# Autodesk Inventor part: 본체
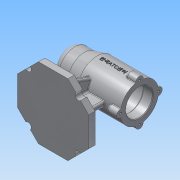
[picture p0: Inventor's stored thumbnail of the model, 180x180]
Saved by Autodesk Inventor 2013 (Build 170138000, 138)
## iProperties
Created: 2019-12
Part Number: 본체
Material: 알루미늄 6061
Document SubType Name: Modeling
Designer: Administrator
Density: 2.71 g/cm^3
Mass: 728.059 g
Surface Area: 716.508 cm^2
Volume: 268.657 cm^3
Author: Administrator
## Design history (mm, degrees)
sketch "스케치1"
  geometry: L1 (-56, 0)-(56, 0); L2 (-56, 0)-(-56, 25); L3 (-56, 25)-(-31, 25); L4 (-31, 25)-(-11, 30); L5 (-11, 30)-(56, 30); L6 (56, 30)-(56, 0); 2 further points
  constraints: 12 end point, 2 parallel, 2 perpendicular, 1 coincident, 1 horizontal, 1 midpoint
  dimensions: "d0" = 112 distance of L1.start L1.end; "d2" = 25 distance from line of L3.end L2; "d3" = 45 distance from line of L2 L4.end; "d4" = 50 diameter of L3 L1; "d5" = 60 diameter of L5 L1
revolve "회전1" sketch "스케치1" stored, may be unused: angle "d6" = 90 deg
node "작업 평면1"
sketch "스케치2" dims "d8" = 112
  geometry: L1 (23.196, 56)-(56, 23.196); L2 (56, 23.196)-(56, -23.196); L3 (56, -23.196)-(23.196, -56); L4 (23.196, -56)-(-23.196, -56); L5 (-23.196, -56)-(-56, -23.196); L6 (-56, -23.196)-(-56, 23.196); L7 (-56, 23.196)-(-23.196, 56); L8 (-23.196, 56)-(23.196, 56); 4 further points
  constraints: 16 end point, 2 coincident, 1 midpoint, 1 vertical alignment, 19 other
extrude "돌출1" join sketch "스케치2" distance "d9" = 10; taper "d10" = 0 deg
sketch "스케치4"
  geometry: L1 (-80, 56)-(-70, 56) reference; L2 (-70, 56)-(-70, -56) reference; L3 (-70, -56)-(-80, -56) reference; L4 (-80, -56)-(-80, 56) reference; L5 (-70, 0)-(0, 0); L6 (0, 0)-(0, -10.522); L7 (0, -10.522)-(-70, -36); L8 (-70, 0)-(-70, -36); C1 r 30 at (0, 0) reference; 1 further point
  constraints: 8 end point, 2 perpendicular, 1 collinear, 1 midpoint, 1 point on line
  dimensions: "d11" = 110 deg angle of L2 L7; "d12" = 20 distance from line of L3 L7.end
extrude "돌출2" join sketch "스케치4" stored distance "d13" = 8; taper "d14" = 0 deg
sketch "스케치5"
  geometry: L1 (-56, -25)-(-56, 25) reference; L2 (-56, 25)-(-31, 25) reference; L3 (-31, 25)-(-11, 30) reference; L4 (-11, 30)-(56, 30) reference; L5 (56, 30)-(56, -30) reference; L6 (56, -30)-(4, -30) reference; L7 (4, -30)-(4, -70) reference; L8 (4, -70)-(56, -70) reference; L9 (56, -70)-(56, -80) reference; L10 (56, -80)-(-56, -80) reference; L11 (-56, -80)-(-56, -70) reference; L12 (-56, -70)-(-4, -70) reference; L13 (-4, -70)-(-4, -30) reference; L14 (-4, -30)-(-11, -30) reference; L15 (-11, -30)-(-31, -25) reference; L16 (-31, -25)-(-56, -25) reference; L17 (31, -70)-(31, 0); L18 (31, 0)-(-5.358, 0); L19 (-5.358, 0)-(-38, -70); L20 (31, -70)-(-38, -70); 1 further point
  constraints: 8 end point, 3 point on line, 2 perpendicular, 1 parallel
  dimensions: "d15" = 115 deg angle of L12 L19; "d16" = 18 distance from line of L11 L19.end; "d17" = 25 distance of L8.end L17.start
extrude "돌출3" join sketch "스케치5" stored distance "d18" = 8; taper "d19" = 0 deg
sketch "스케치6"
  geometry: L1 (-56, -25)-(-56, 25) reference; L2 (-56, 25)-(-31, 25) reference; L3 (-31, 25)-(-11, 30) reference; L4 (-11, 30)-(56, 30) reference; L5 (56, 30)-(56, -30) reference; L6 (56, -30)-(31, -30) reference; L7 (31, -30)-(31, -70) reference; L8 (31, -70)-(56, -70) reference; L9 (56, -70)-(56, -80) reference; L10 (56, -80)-(-56, -80) reference; L11 (-56, -80)-(-56, -70) reference; L12 (-56, -70)-(-38, -70) reference; L13 (-38, -70)-(-18.476, -28.131) reference; L14 (-18.476, -28.131)-(-31, -25) reference; L15 (-31, -25)-(-56, -25) reference; L16 (-56, 0)-(56, 0); L17 (-50, 0)-(-50, 10.5); L18 (-50, 10.5)-(-47, 10.5); L19 (-47, 10.5)-(-47, 16); L20 (-47, 16)-(-43, 16); L21 (-43, 16)-(-43, 17.5); L22 (-43, 17.5)-(-25, 17.5); L23 (-25, 17.5)-(-25, 21); L24 (-25, 21)-(-13, 21); L25 (-13, 21)-(-13, 24); L26 (-13, 24)-(41, 24); L27 (41, 24)-(41, 21); L28 (41, 21)-(56, 21); L29 (56, 0)-(56, 21); 1 further point
  constraints: 28 end point, 10 parallel, 3 perpendicular, 2 midpoint, 2 point on line
  dimensions: "d20" = 21 diameter of L18 L16; "d22" = 32 diameter of L20 L16; "d23" = 35 diameter of L22 L16; "d24" = 42 diameter of L24 L16; "d25" = 48 diameter of L26 L16; "d26" = 42 diameter of L28 L16; "d27" = 3 distance between parallel lines of L19 L17; "d28" = 4 distance between parallel lines of L21 L19; "d29" = 18 distance between parallel lines of L23 L21; "d30" = 15 distance between parallel lines of L5 L27; "d31" = 12 distance between parallel lines of L23 L25; "d32" = 54 distance between parallel lines of L27 L25
revolve "회전2" sketch "스케치6" stored, may be unused: angle "d33" = 90 deg
sketch "스케치7"
  geometry: C1 r 21 at (0, 0) reference; C2 r 6 at (0, 30); 1 further point
  constraints: 2 vertical alignment, 1 centre point, 1 other
  dimensions: "d34" = 12 diameter of C2
extrude "돌출4" join sketch "스케치7" distance "d36" = 16; taper "d37" = 0 deg
sketch "스케치8"
  geometry: L1 (23.196, -56)-(56, -23.196) reference; L2 (23.196, 56)-(-23.196, 56) reference; L3 (-70.421, 0)-(0, 0); L4 (0, 0)-(-59.714, 59.714); C1 r 5 at (-39.598, 39.598); 1 further point
  constraints: 4 end point, 1 centre point, 1 coincident, 1 parallel, 1 point on line, 4 other
  dimensions: "d42" = 45 deg angle of L3 L4; "d43" = 10 diameter of C1
extrude "돌출5" cut sketch "스케치8" stored distance "d45" = 16; taper "d46" = 0 deg
sketch "스케치9"
  geometry: A1 r 6 centre (0, 0) between (5.97, -0.6) and (-5.97, -0.6) reference; A2 r 6 centre (-30, -30) between (-29.4, -24.03) and (-29.4, -35.97) reference; A3 r 6 centre (0, -60) between (-5.97, -59.4) and (5.97, -59.4) reference; A4 r 6 centre (30, -30) between (29.4, -35.97) and (29.4, -24.03) reference
hole "구멍1" sketch "스케치9" at (0, 0), (-30, -30), (0, -60), (30, -30) diameter "d50" = 3.242; stored, may be unused: countersink angle "d54" = 90 deg, drill point angle "d56" = 118 deg; dims "d51" = 8, "d52" = 4, "d53" = 2, "d55" = 11
node "작업 평면2"
sketch "스케치10"
  geometry: L1 (56, 5.97)-(56, 29.4) reference; 2 further points
  constraints: 1 horizontal alignment, 1 other
  dimensions: "d58" = 41 distance from line of L1 point (15, 0)
feature "엠보싱1" sketch "스케치10" dims "d59" = 0.5, "d60" = 0
fillet "모깎기1" dims "d61" = 10
fillet "모깎기2" dims "d62" = 3
fillet "모깎기3" dims "d63" = 1
fillet "모깎기4" dims "d64" = 0.3
fillet "모깎기5" dims "d65" = 3
fillet "모깎기6" dims "d66" = 3
fillet "모깎기7" dims "d67" = 3
fillet "모깎기8" dims "d68" = 3
fillet "모깎기9" dims "d69" = 1
chamfer "모따기1" distance "d70" = 1; stored, may be unused: second distance "d71" = 2, angle "d72" = 45 deg
node "솔리드1"
mirror "대칭1"
pattern_circular "원형 패턴1" dims angle "d39" = 360 deg
pattern_circular "원형 패턴2" dims angle "d48" = 360 deg
node "절단 모서리 투영1"
node "절단 모서리 투영2"
node "절단 모서리 투영3"
other parameters: "d57" = 94.25
